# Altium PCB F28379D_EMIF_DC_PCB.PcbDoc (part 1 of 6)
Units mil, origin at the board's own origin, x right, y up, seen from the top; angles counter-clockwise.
Board outline 3000 x 1480 mil, 6 copper layers (Top Layer, Signal Layer 1, Signal Layer 2, Signal Layer 3, Signal Layer 4, Bottom Layer), stack 61.4 mil thick; 51 components, 68 nets, 414 pads, 205 vias.
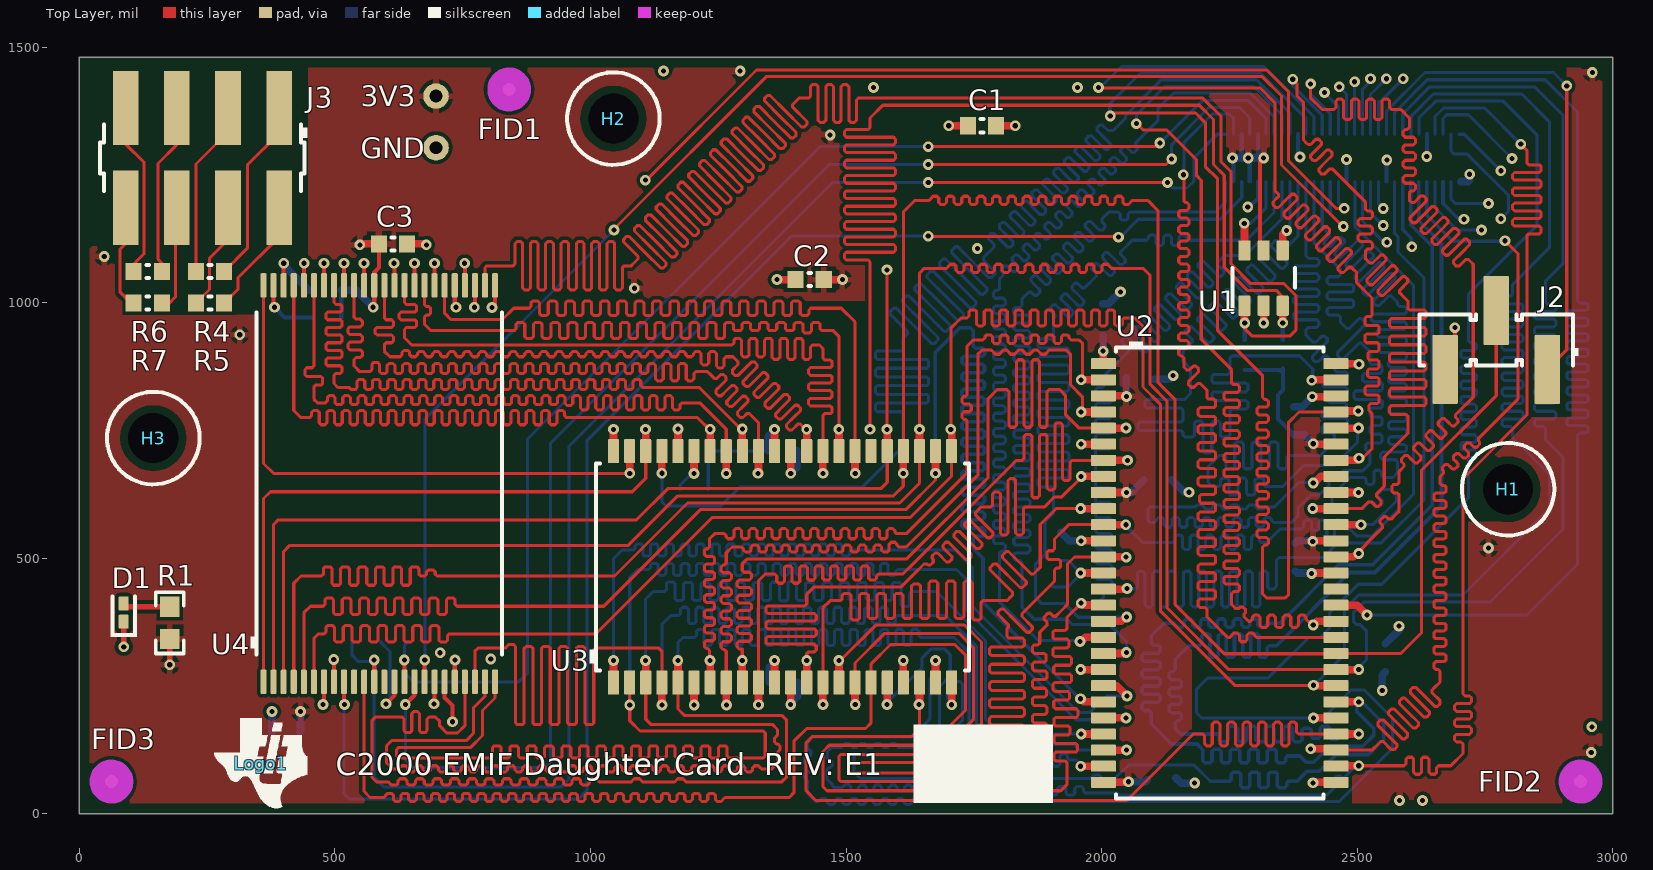
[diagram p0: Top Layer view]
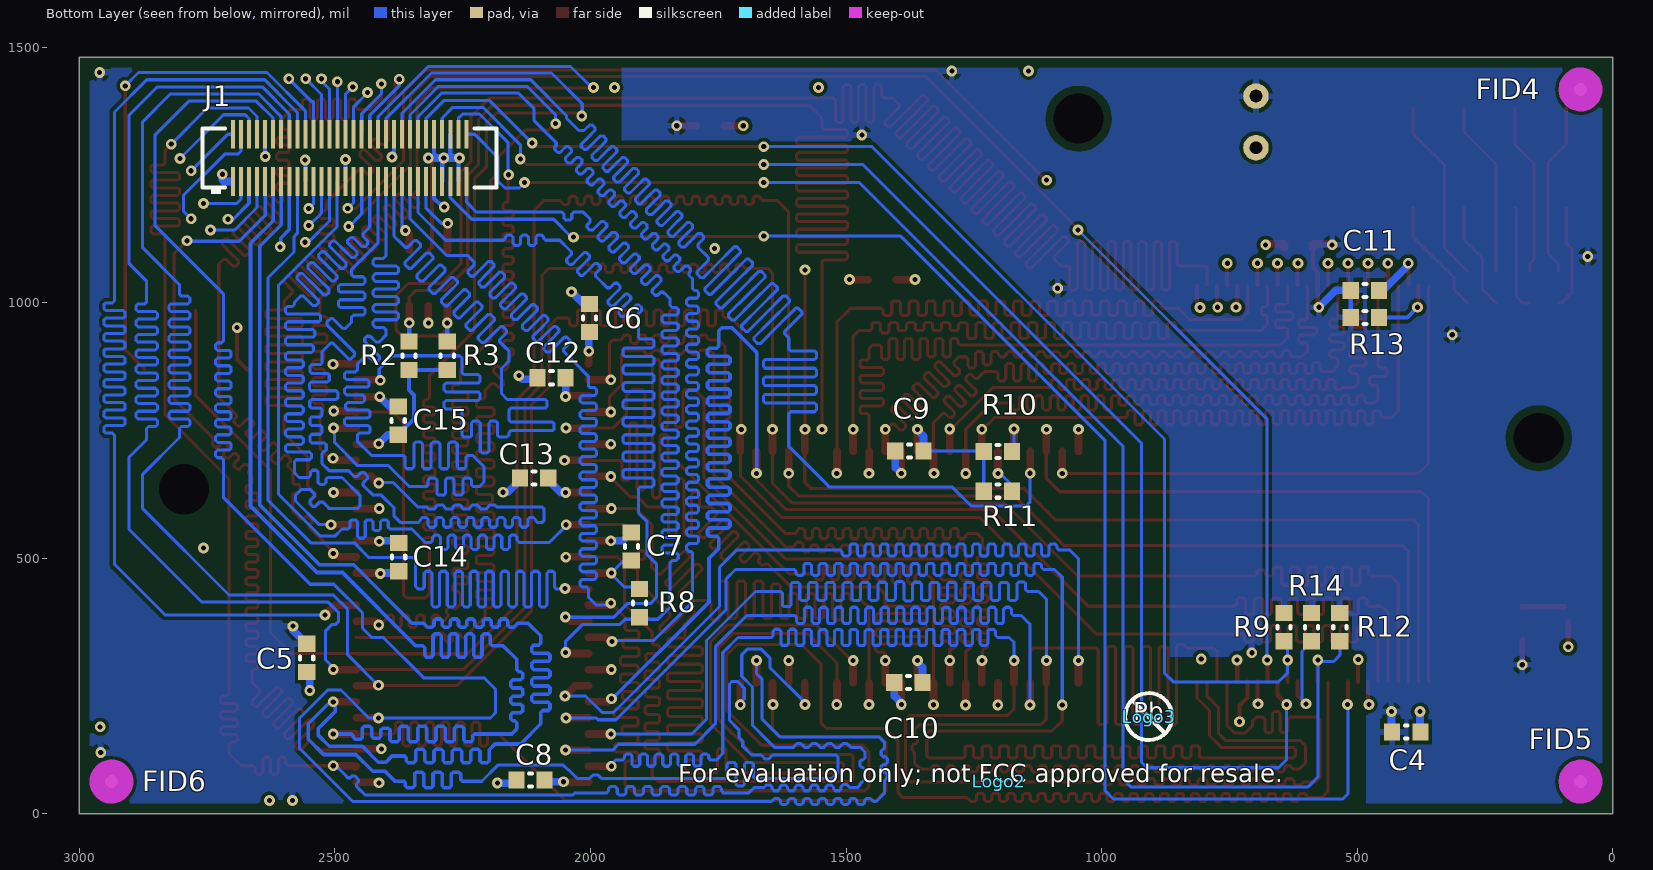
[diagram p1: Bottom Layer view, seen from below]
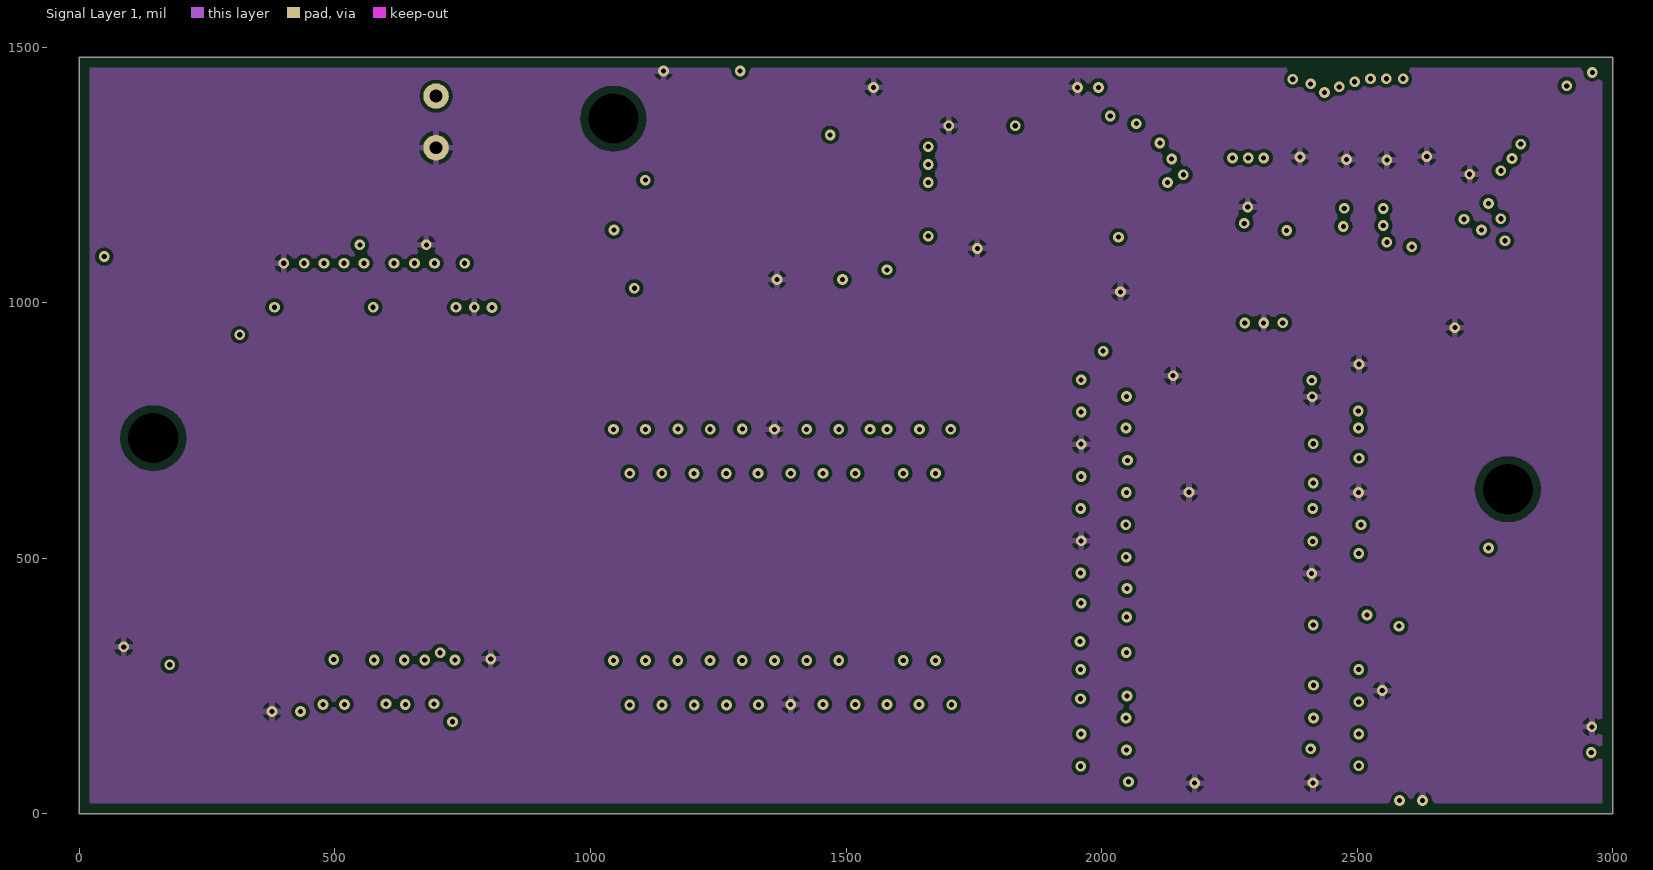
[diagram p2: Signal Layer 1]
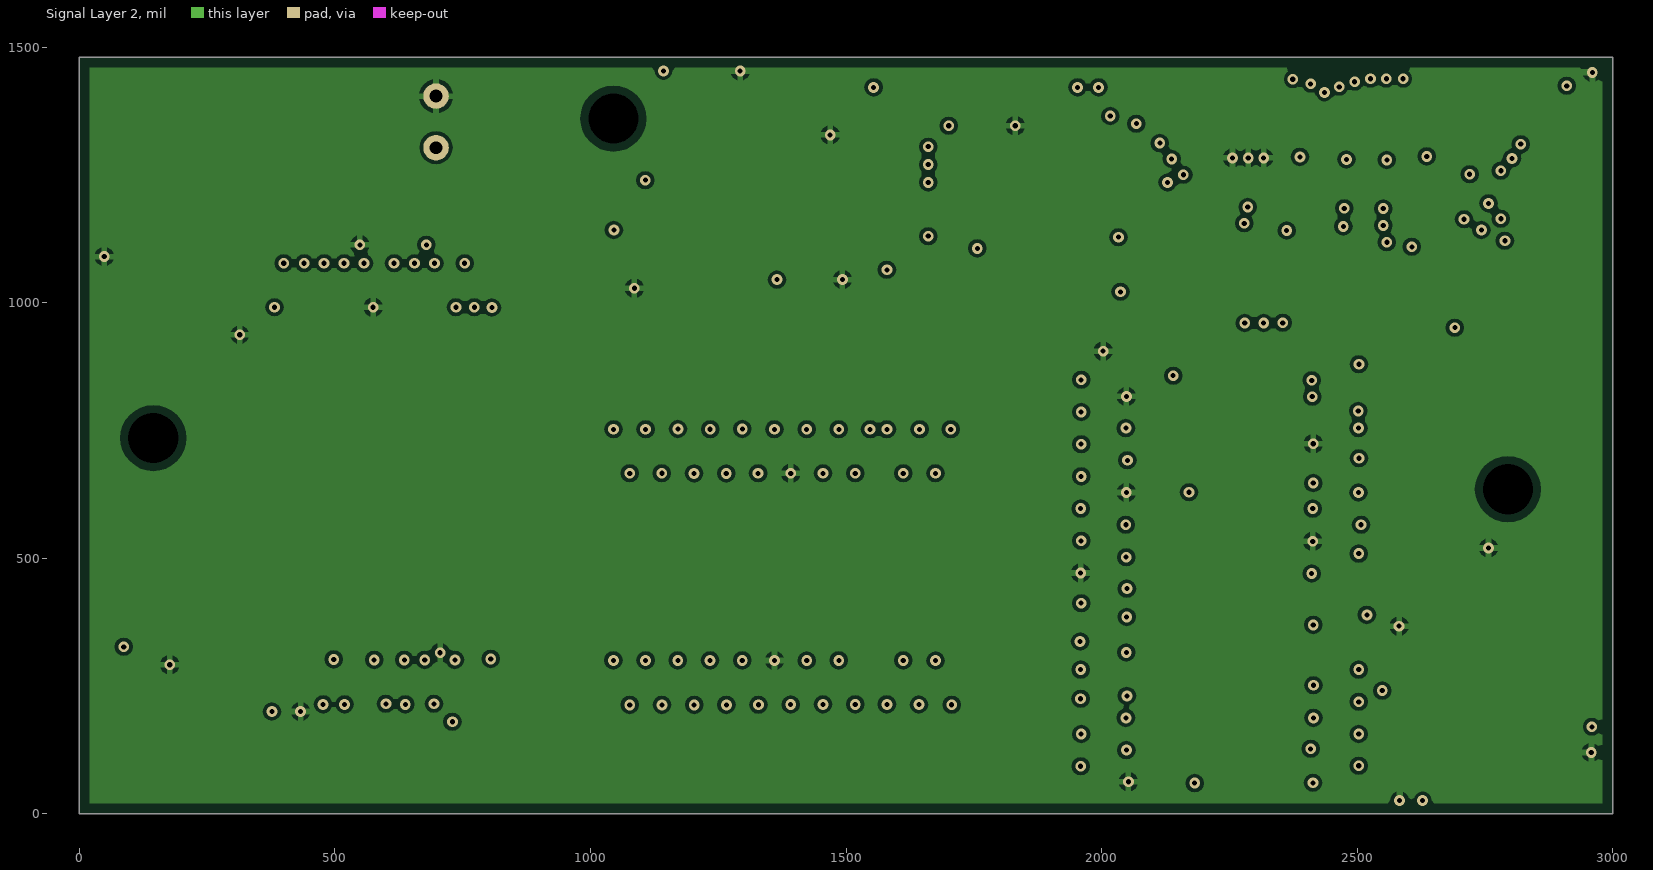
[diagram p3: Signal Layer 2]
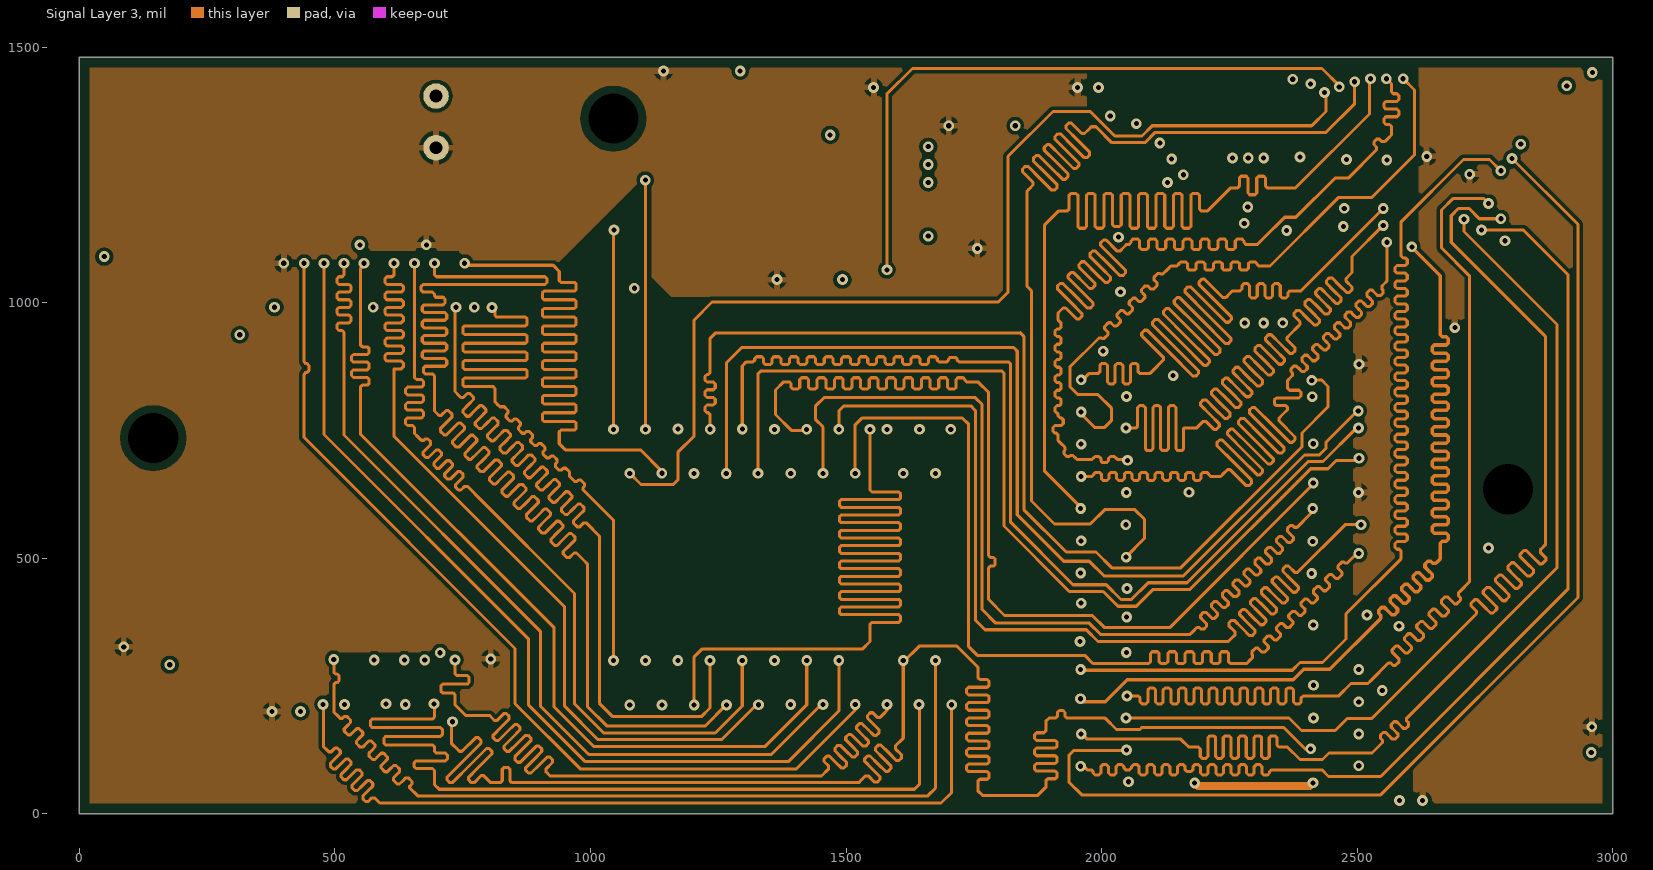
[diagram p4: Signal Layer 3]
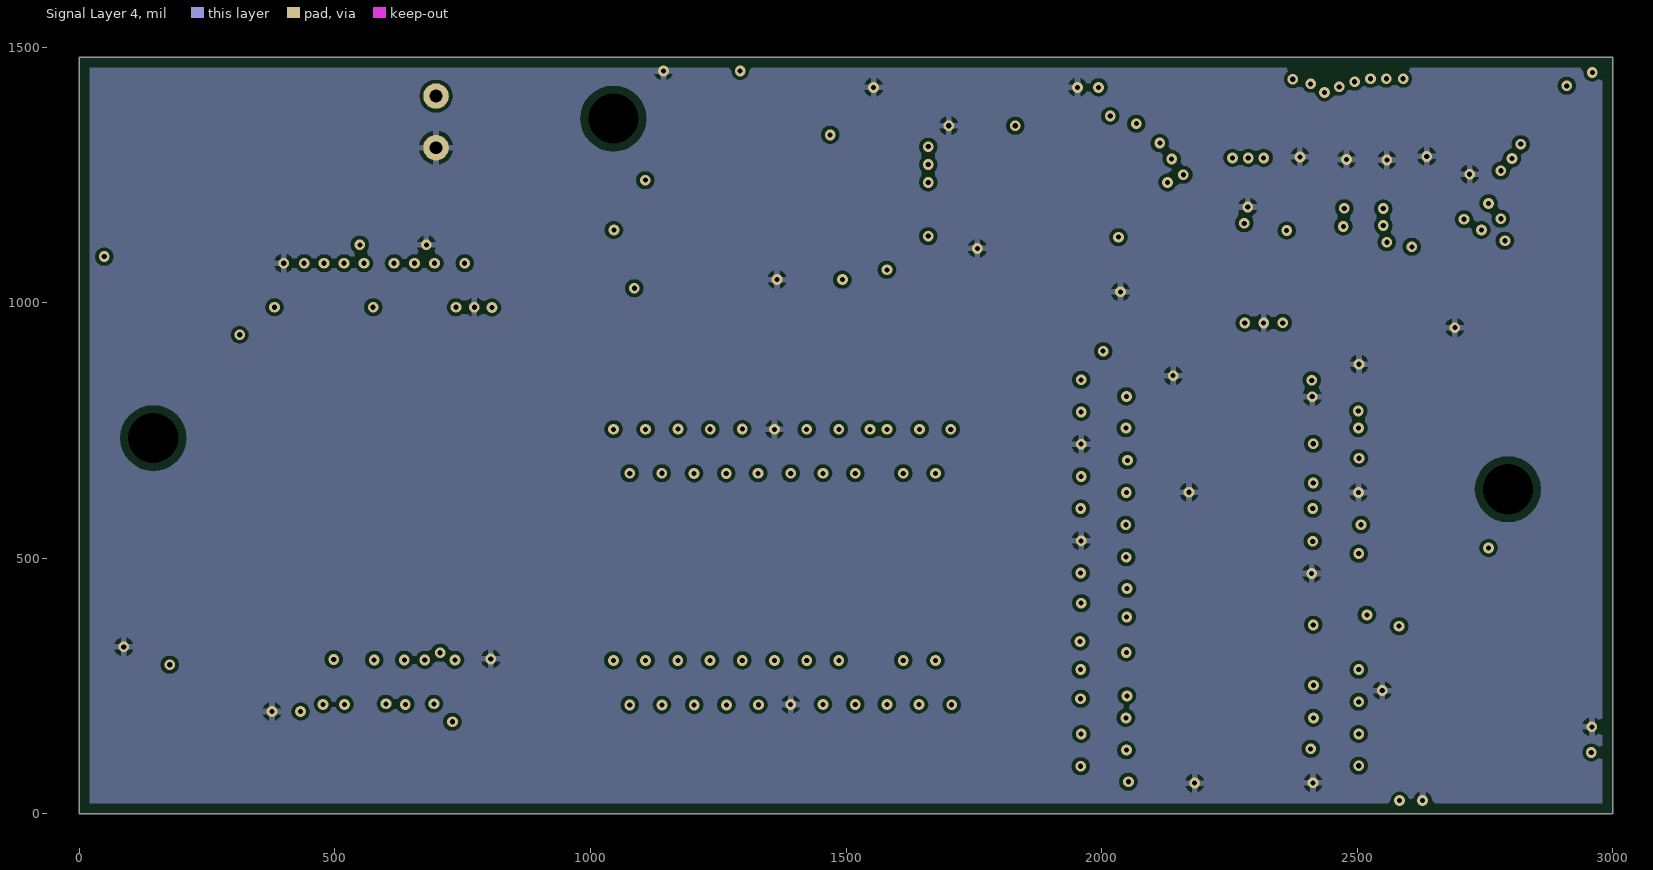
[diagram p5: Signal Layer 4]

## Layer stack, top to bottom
Top Solder: solder mask 0.5, Solder Resist, Dk 3.5
Top Layer: signal copper 1.4
Dielectric 1: prepreg 7, FR-4, Dk 4.2
Signal Layer 1: signal copper 1.4
Dielectric 2: core 14, FR-4, Dk 4.2
Signal Layer 2: signal copper 1.4
Dielectric 4: prepreg 11, FR-4, Dk 4.2
Signal Layer 3: signal copper 1.4
Dielectric 5: core 14, FR-4, Dk 4.2
Signal Layer 4: signal copper 1.4
Dielectric 3: prepreg 7, FR-4, Dk 4.2
Bottom Layer: signal copper 1.4
Bottom Solder: solder mask 0.5, Solder Resist, Dk 3.5

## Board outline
0,0 3000,0 3000,1480 0,1480

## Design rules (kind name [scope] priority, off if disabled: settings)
AcuteAngle [All] p1: minimum=4.50000000000000E+0001 checktracksonly=FALSE
AssemblyTestPointUsage [All] p1: valid=2
BoardOutlineClearance BoardOutlineClearance_MountingHoles [OnCopper and InComponentClass('Mounting Holes')] p1: gap=40
BoardOutlineClearance BoardOutlineClearance_Poly [OnCopper and IsPoly] p2: gap=20
BoardOutlineClearance [OnCopper and Not InComponentClass('Logo') and not InComponentClass('FiducialMark') and not InRegion(1000,500,4000,800) and not InPoly] p3: gap=15
Clearance Clearance_Essentra [HasFootprint('Essentra_MDLSP1-04M-01')] p1: gap=15
Clearance Clearance_Keepouts [((IsTrack Or IsArc) And Not InPoly) And IsFree and IsKeepOut vs ((IsTrack Or IsArc) And Not InPoly) And IsFree and IsKeepOut] p2: gap=0
Clearance Clearance_Poly [InPolygon] p3: gap=7
Clearance [All] p4: gap=7
ComponentClearance ComponentClearance_MountingHoles_FiducialMarks [InComponentClass('Mounting Holes') vs InComponentClass('FiducialMark')] p1: gap=50 collisioncheckmode=3 verticalgap=10 showdistances=FALSE
ComponentClearance ComponentClearance_Shunt [InComponentClass('Header') vs InComponentClass('Shunt')] p2: gap=0 collisioncheckmode=3 verticalgap=0 showdistances=FALSE
ComponentClearance ComponentClearance_Logo [InComponentClass('Logo')] p3: gap=50 collisioncheckmode=3 verticalgap=10 showdistances=FALSE
ComponentClearance ComponentClearance_ScrewToNut [(HasFootprint('NY PMS 440 0025 PH')) vs (HasFootprint('Keystone_1902C'))] p4: gap=5 collisioncheckmode=3 verticalgap=10 showdistances=FALSE
ComponentClearance ComponentClearance_MountingHoles [InComponentClass('Mounting Holes')] p5: gap=250 collisioncheckmode=3 verticalgap=100000 showdistances=FALSE
ComponentClearance ComponentClearance_SmallPassives [HasFootprint('0201*') or HasFootprint('0402*') or HasFootprint('0508') or HasFootprint('0603*') or HasFootprint('0612') or HasFootprint('0805*') or HasFootprint('0815*') or HasFootprint('0830*') or HasFootprint('1206*') or HasFootprint('1210*') or HasFootprint('1808*') or HasFootprint('1812*') or HasFootprint('1825*') or HasFootprint('2010*') or HasFootprint('2220*') or HasFootprint('2225*') or HasFootprint('2512*') or HasFootprint('2728*') or HasFootprint('3518*') vs HasFootprint('0201*') or HasFootprint('0402*') or HasFootprint('0508') or HasFootprint('0603*') or HasFootprint('0612') or HasFootprint('0805*') or HasFootprint('0815*') or HasFootprint('0830*') or HasFootprint('1206*') or HasFootprint('1210*') or HasFootprint('1808*') or HasFootprint('1812*') or HasFootprint('1825*') or HasFootprint('2010*') or HasFootprint('2220*') or HasFootprint('2225*') or HasFootprint('2512*') or HasFootprint('2728*') or HasFootprint('3518*')] p6: gap=14.96 collisioncheckmode=3 verticalgap=10 showdistances=FALSE
ComponentClearance ComponentClearance_THtoSMT [IsThruComponent vs IsSMTComponent] p7: gap=40 collisioncheckmode=3 verticalgap=30 showdistances=FALSE
ComponentClearance ComponentClearance_THtoTH [IsThruComponent vs IsThruComponent] p8: gap=30 collisioncheckmode=3 verticalgap=30 showdistances=FALSE
ComponentClearance [All] p9: gap=30 collisioncheckmode=3 verticalgap=10 showdistances=FALSE
DiffPairsRouting [All] p1: maxlimit=100 minlimit=10 mostfreqgap=10 toplayer_minwidth=15 toplayer_maxwidth=15 toplayer_prefwidth=15 midlayer1_minwidth=15 midlayer1_maxwidth=15 midlayer1_prefwidth=15 midlayer2_minwidth=15 midlayer2_maxwidth=15 midlayer2_prefwidth=15 midlayer3_minwidth=15 midlayer3_maxwidth=15 midlayer3_prefwidth=15 midlayer4_minwidth=15 midlayer4_maxwidth=15 midlayer4_prefwidth=15 bottomlayer_minwidth=15 bottomlayer_maxwidth=15 bottomlayer_prefwidth=15 maxuncoupledlength=1000
FabricationTestPointUsage TestPointUsage [All] p1: valid=2 allowmultiple=FALSE
FabricationTestpoint Testpoint [All] p1: side=3 testpointundercomponent=TRUE minsize=40 maxsize=100 preferedsize=60 minholesize=0 maxholesize=40 preferedholesize=32 testpointgrid=1 allowsidetop=TRUE allowsidebottom=TRUE usegrid=TRUE gridtolerance=0.01
FanoutControl Fanout_LCC [IsLCC] p1: bgadir=Out bgaviamode=Centered fanoutstyle=Auto fanoutdirection=Alternating viagrid=1 // Fanout_LCC (Default Rule)
FanoutControl Fanout_BGA [IsBGA] p2: bgadir=Out bgaviamode=Centered fanoutstyle=Auto fanoutdirection=Alternating viagrid=1 // Fanout_BGA (Default Rule)
FanoutControl Fanout_Default [All] p4: bgadir=Out bgaviamode=Centered fanoutstyle=Auto fanoutdirection=Alternating viagrid=1 // Fanout_Default (Default Rule)
FanoutControl Fanout_Small [(CompPinCount < 5)] p5: bgadir=Out bgaviamode=Centered fanoutstyle=Auto fanoutdirection=OutThenIn viagrid=1 // Fanout_Small (Default Rule)
HoleSize [All] p1: absolutevalues=TRUE maxlimit=251 minlimit=7.87 maxpercent=80.000 minpercent=20.000
MatchedLengths "Matched Length" [InNetClass('FLASH_Net')] p1: tolerance=30 checknetsindiffpair=FALSE checkdiffpairvsdiffpair=TRUE checkxsignals=TRUE checkothers=TRUE
MinimumAnnularRing MinimumAnnularRing_ThermalPadVias [IsVia and InAnyComponent] p1: minimumring=5.91
MinimumAnnularRing [All] p2: minimumring=5
MinimumSolderMaskSliver MinimumSolderMaskSliver_Logo [InComponentClass('Logo') vs InComponentClass('Logo')] p1: minsoldermaskwidth=0.7
MinimumSolderMaskSliver [All] p2: minsoldermaskwidth=3.8
PlaneClearance [All] p1: clearance=8
PlaneConnect [All] p1: planeconnectstyle=Relief reliefexpansion=10 reliefentries=4 reliefconductorwidth=12 reliefairgap=8
PolygonConnect [All] p1: connectstyle=Relief reliefconductorwidth=12 reliefentries=4 polygonreliefangle="90 Angle" airgapwidth=8
RoutingVias ThermalPadVias [IsVia and InAnyComponent] p1: holewidth=7.87 width=19.68 viastyle="Through Hole" minholewidth=7.87 minwidth=19.68 maxholewidth=12.99 maxwidth=23.62
RoutingVias [All] p2: holewidth=10 width=20 viastyle="Through Hole" minholewidth=7.87 minwidth=20 maxholewidth=40 maxwidth=65
SilkToBoardRegionClearance [Not ((IsComment or IsDesignator) And (Hide <> 'False')) and not InRegion(1000,500,4000,800)] p1:
SilkToSilkClearance SilkToSilkClearance_Pb-FreeLogo [(HasFootprint('Pb-Free_Overlay_Medium') OR HasFootprint('Pb-Free_Overlay_Small')) vs (HasFootprint('Pb-Free_Overlay_Medium') OR HasFootprint('Pb-Free_Overlay_Small'))] p1: silktosilkclearance=0
SilkToSilkClearance [All] p2: silktosilkclearance=4
SilkToSolderMaskClearance SilkToComponentPadClearance [(IsPad or IsFill or IsRegion) and InAnycomponent] p1: minsilkscreentomaskgap=5 clearancetoexposedcopper=TRUE
SilkToSolderMaskClearance "Silk to Solder Mask Opening" [All] p2: minsilkscreentomaskgap=4 clearancetoexposedcopper=FALSE
SolderMaskExpansion [All] p1: expansion=1.97
Width "Power Route" [InNetClass('Power')] p1: maxlimit=20 minlimit=6 preferedwidth=15
Width [All] p2: maxlimit=100 minlimit=6 preferedwidth=6 checkconnectedcopper=TRUE
14 further rules are at their usual default settings.

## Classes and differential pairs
component class Logo: Logo1
component class FiducialMark: FID1 FID2 FID3 FID4 FID5 FID6
net class FLASH_Net: /EM_OE /EM_WE EM_A0 EM_A1 EM_A2 EM_A3 EM_A4 EM_A5 EM_A6 EM_A7 EM_A8 EM_A9 EM_A10 EM_A11 EM_BA1 EM_D0 EM_D1 EM_D2 EM_D3 EM_D4 EM_D5 EM_D6 EM_D7 EM_D8 EM_D9 EM_D10 EM_D11 EM_D12 EM_D13 EM_D14 EM_D15
net class ASRAM_Net: /EM_OE /EM_WE EM_A0 EM_A1 EM_A2 EM_A3 EM_A4 EM_A5 EM_A6 EM_A7 EM_A8 EM_A9 EM_A10 EM_A11 EM_BA1 EM_D0 EM_D1 EM_D2 EM_D3 EM_D4 EM_D5 EM_D6 EM_D7 EM_D8 EM_D9 EM_D10 EM_D11 EM_D12 EM_D13 EM_D14 EM_D15
net class SDRAM_Net: /EM_CS0 /EM_WE EM_A0 EM_A1 EM_A2 EM_A3 EM_A4 EM_A5 EM_A6 EM_A7 EM_A8 EM_A9 EM_A10 EM_A11 EM_A13_CAS EM_A14_RAS EM_A15_DQM0 EM_A16_DQM1 EM_BA0 EM_BA1 EM_CLK EM_D0 EM_D1 EM_D2 EM_D3 EM_D4 EM_D5 EM_D6 EM_D7 EM_D8 EM_D9 EM_D10 EM_D11 EM_D12 EM_D13 EM_D14 EM_D15 EM_SDCKE
net class Power_Net: GND VCC_3V3
component class F28379D_EMIF_EVM_Hardware: FID1 FID2 FID3 FID4 FID5 FID6 H1 H2 H3 Logo1 Logo2 Logo3
component class F28379D_EMIF_Memory: 3V3 C1 C2 C3 C4 C5 C6 C7 C8 C9 C10 C11 C12 C13 C14 C15 D1 GND J1 J2 J3 R1 R2 R3 R4 R5 R6 R7 R8 R9 R10 R11 R12 R13 R14 R? TP2 U1 U2 U3 U4
component class Header: J2 J3

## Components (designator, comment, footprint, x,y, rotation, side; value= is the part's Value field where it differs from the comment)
3V3 "TESTPOINT" TP_50MIL-25MILHOLE 698,1404 r0 top
C1 "C1608X5R1A106M080AC" 0603L 1766,1346 r180 top
C2 "C1608X5R1A106M080AC" 0603L 1429,1045 r180 top
C3 "C1608X5R1A106M080AC" 0603L 614,1115 r0 top
C4 "C1608X5R1A106M080AC" 0603L 404,160 r180 bottom
C5 "C1608X5R1A106M080AC" 0603L 2555,305 r270 bottom
C6 "GRM188R71A225KE15D" 0603L 2002,970 r90 bottom
C7 "GRM188R71A225KE15D" 0603L 1920,523 r90 bottom
C8 "GRM188R71A225KE15D" 0603L 2117,66 r0 bottom
C9 "GRM188R71A225KE15D" 0603L 1376,710 r180 bottom
C10 "GRM188R71A225KE15D" 0603L 1378,257 r0 bottom
C11 "GRM188R71A225KE15D" 0603L 485,1024 r180 bottom
C12 "GRM188R71A225KE15D" 0603L 2076,853 r0 bottom
C13 "GRM188R71A225KE15D" 0603L 2110,657 r0 bottom
C14 "GRM188R71A225KE15D" 0603L 2375,502 r270 bottom
C15 "GRM188R71A225KE15D" 0603L 2376,769 r90 bottom
D1 "APHHS1005CGCK" APHHS1005_Green 87,393.5 r270 top
FID1 "Fiducial" Fiducial6.4-20 841,1417 r0 top
FID2 "Fiducial" Fiducial6.4-20 2937,63 r0 top
FID3 "Fiducial" Fiducial6.4-20 63,63 r0 top
FID4 "Fiducial" Fiducial6.4-20 63,1417 r180 bottom
FID5 "Fiducial" Fiducial6.4-20 63,63 r180 bottom
FID6 "Fiducial" Fiducial6.4-20 2937,63 r180 bottom
GND "TESTPOINT" TP_50MIL-25MILHOLE 698,1303 r0 top
H1 "MDLSP1-04M-01" Essentra_MDLSP1-04M-01 2795,635 r0 top locked
H2 "MDLSP1-04M-01" Essentra_MDLSP1-04M-01 1045,1360 r0 top locked
H3 "MDLSP1-04M-01" Essentra_MDLSP1-04M-01 145,735 r0 top locked
J1 "DF40HC(4.0)-60DS-0.4V(51)" Hirose_DF40HC-4_0-60DS-0_4V_Reverse 2471,1283 r180 bottom
J2 "TSM-103-01-L-SV-P-TR" Samtec_TSM-103-01-x-SV-P 2772,927 r180 top
J3 "TSM-104-01-L-DV" Samtec_TSM-104-01-x-DV 241,1283 r270 top
Logo1 "Texas Instruments" TI_Symbol_Overlay_Small 355,99 r0 top
Logo2 "FCC disclaimer" FCC_disclaimer 1201,64 r180 bottom
Logo3 "Pb-Free Symbol" Pb-Free_Overlay_Small 908,190 r180 bottom
R1 "CRCW0603820RJNEA" 0603 177,373.5 r270 top
R2 "RC0603JR-0747KL" 0603L 2355,896 r270 bottom
R3 "RC0603JR-0747KL" 0603L 2280,896 r270 bottom
R4 "CRCW06030000Z0EA" 0603L 256,1061 r0 top
R5 "CRCW06030000Z0EA" 0603L 256,999 r180 top
R6 "CRCW06030000Z0EA" 0603L 134,1061 r0 top
R7 "CRCW06030000Z0EA" 0603L 134,999 r180 top
R8 "RC0603JR-0747KL" 0603L 1904,412 r90 bottom
R9 "RC0603JR-0747KL" 0603L 643,365 r90 bottom
R10 "RC0603JR-0747KL" 0603L 1203,709 r180 bottom
R11 "RC0603JR-0747KL" 0603L 1203,631 r180 bottom
R12 "RC0603JR-0747KL" 0603L 534,365 r270 bottom
R13 "RC0603JR-0747KL" 0603L 485,971 r180 bottom
R14 "RC0603JR-0747KL" 0603L 589,365 r270 bottom
U1 "TS5A3159DBVR" DBV0006A_N 2317,1048 r90 top
U2 "AS4C16M16SA-6TIN" TSOP-2_54 2231,471 r0 top
U3 "IS61WV25616EDBLL-10TLI" TSOP-2_44 1376,483 r90 top
U4 "S29AL016J70TFI020" TSOP-48 587,646 r90 top

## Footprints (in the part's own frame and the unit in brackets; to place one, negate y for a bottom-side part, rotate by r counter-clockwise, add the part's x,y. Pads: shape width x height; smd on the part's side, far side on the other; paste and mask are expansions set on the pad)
0603 [mm] "0603 from SM-752 data"
  rect 1x0.95 smd: 1(-0.8,0) 2(0.8,0)
  silkscreen extent -1.52,-0.69 1.52,0.69, body extent -0.87,-0.47 0.87,0.47, height 1
0603L [mm] "0603 from SM-752 data"
  rect 0.8x0.85 smd: 1(-0.7,0) 2(0.7,0)
  silkscreen extent -0.07,-0.33 0.07,0.33, body extent -0.87,-0.47 0.87,0.47, height 1
APHHS1005_Green [mm] "SMD, 2-Leads, Body 1x0.5mm"
  rrect20% 0.7x0.5 smd: 1(-0.45,0) 2(0.45,0)
  silkscreen extent -0.8,-0.65 1.2,0.65, body extent -0.5,-0.25 0.5,0.25, height 0.5
DBV0006A_N [mm] "SOT23, 6-Leads, Body 2.9x1.6mm, Pitch 0.95mm, Lead Span 2.8mm, IPC Medium Density"
  rrect17% 1x0.6 smd: 1(-1.375,0.95) 2(-1.375,0) 3(-1.375,-0.95) 4(1.375,-0.95) 5(1.375,0) 6(1.375,0.95)
  silkscreen extent -1.67,-1.55 0.5,1.55, body extent -1.42,-1.46 1.42,1.46, height 1.12
Essentra_MDLSP1-04M-01 [mm] "Board Support Snap Lock"
  round 0 hole 2.5 unplated: 1(0,0)
  silkscreen extent -2.3,-2.3 2.3,2.3, body extent -2.3,-2.3 2.3,2.3, height 7.7
FCC_disclaimer [mil]
Fiducial6.4-20 [mil]
  round 25 smd mask+26.87: 1(0,0)
  Top Layer keep-out circle w46.37: c0,0 r19.68
Hirose_DF40HC-4_0-60DS-0_4V_Reverse [mm] "Receptacle, 0.4mm, 30x2, SMT"
  rect 0.2x0.7 on Bottom Paste mask-1: 1(-5.8,-1.54) 2(-5.8,1.54) 3(-5.4,-1.54) 4(-5.4,1.54) 5(-5,-1.54) 6(-5,1.54) 7(-4.6,-1.54) 8(-4.6,1.54) 9(-4.2,-1.54) 10(-4.2,1.54) 11(-3.8,-1.54) 12(-3.8,1.54) 13(-3.4,-1.54) 14(-3.4,1.54) 15(-3,-1.54) 16(-3,1.54) 17(-2.6,-1.54) 18(-2.6,1.54) 19(-2.2,-1.54) 20(-2.2,1.54) 21(-1.8,-1.54) 22(-1.8,1.54) 23(-1.4,-1.54) 24(-1.4,1.54) 25(-1,-1.54) 26(-1,1.54) 27(-0.6,-1.54) 28(-0.6,1.54) 29(-0.2,-1.54) 30(-0.2,1.54) 31(0.2,-1.54) 32(0.2,1.54) 33(0.6,-1.54) 34(0.6,1.54) 35(1,-1.54) 36(1,1.54) 37(1.4,-1.54) 38(1.4,1.54) 39(1.8,-1.54) 40(1.8,1.54) 41(2.2,-1.54) 42(2.2,1.54) 43(2.6,-1.54) 44(2.6,1.54) 45(3,-1.54) 46(3,1.54) 47(3.4,-1.54) 48(3.4,1.54) 49(3.8,-1.54) 50(3.8,1.54) 51(4.2,-1.54) 52(4.2,1.54) 53(4.6,-1.54) 54(4.6,1.54) 55(5,-1.54) 56(5,1.54) 57(5.4,-1.54) 58(5.4,1.54) 59(5.8,-1.54) 60(5.8,1.54)
  rect 0.2x0.7 on Bottom Solder mask-1: 1(-5.8,-1.54) 2(-5.8,1.54) 3(-5.4,-1.54) 4(-5.4,1.54) 5(-5,-1.54) 6(-5,1.54) 7(-4.6,-1.54) 8(-4.6,1.54) 9(-4.2,-1.54) 10(-4.2,1.54) 11(-3.8,-1.54) 12(-3.8,1.54) 13(-3.4,-1.54) 14(-3.4,1.54) 15(-3,-1.54) 16(-3,1.54) 17(-2.6,-1.54) 18(-2.6,1.54) 19(-2.2,-1.54) 20(-2.2,1.54) 21(-1.8,-1.54) 22(-1.8,1.54) 23(-1.4,-1.54) 24(-1.4,1.54) 25(-1,-1.54) 26(-1,1.54) 27(-0.6,-1.54) 28(-0.6,1.54) 29(-0.2,-1.54) 30(-0.2,1.54) 31(0.2,-1.54) 32(0.2,1.54) 33(0.6,-1.54) 34(0.6,1.54) 35(1,-1.54) 36(1,1.54) 37(1.4,-1.54) 38(1.4,1.54) 39(1.8,-1.54) 40(1.8,1.54) 41(2.2,-1.54) 42(2.2,1.54) 43(2.6,-1.54) 44(2.6,1.54) 45(3,-1.54) 46(3,1.54) 47(3.4,-1.54) 48(3.4,1.54) 49(3.8,-1.54) 50(3.8,1.54) 51(4.2,-1.54) 52(4.2,1.54) 53(4.6,-1.54) 54(4.6,1.54) 55(5,-1.54) 56(5,1.54) 57(5.4,-1.54) 58(5.4,1.54) 59(5.8,-1.54) 60(5.8,1.54)
  rect 0.2x1.43 smd paste-1 mask-1: 1(-5.8,-1.175) 2(-5.8,1.175) 3(-5.4,-1.175) 4(-5.4,1.175) 5(-5,-1.175) 6(-5,1.175) 7(-4.6,-1.175) 8(-4.6,1.175) 9(-4.2,-1.175) 10(-4.2,1.175) 11(-3.8,-1.175) 12(-3.8,1.175) 13(-3.4,-1.175) 14(-3.4,1.175) 15(-3,-1.175) 16(-3,1.175) 17(-2.6,-1.175) 18(-2.6,1.175) 19(-2.2,-1.175) 20(-2.2,1.175) 21(-1.8,-1.175) 22(-1.8,1.175) 23(-1.4,-1.175) 24(-1.4,1.175) 25(-1,-1.175) 26(-1,1.175) 27(-0.6,-1.175) 28(-0.6,1.175) 29(-0.2,-1.175) 30(-0.2,1.175) 31(0.2,-1.175) 32(0.2,1.175) 33(0.6,-1.175) 34(0.6,1.175) 35(1,-1.175) 36(1,1.175) 37(1.4,-1.175) 38(1.4,1.175) 39(1.8,-1.175) 40(1.8,1.175) 41(2.2,-1.175) 42(2.2,1.175) 43(2.6,-1.175) 44(2.6,1.175) 45(3,-1.175) 46(3,1.175) 47(3.4,-1.175) 48(3.4,1.175) 49(3.8,-1.175) 50(3.8,1.175) 51(4.2,-1.175) 52(4.2,1.175) 53(4.6,-1.175) 54(4.6,1.175) 55(5,-1.175) 56(5,1.175) 57(5.4,-1.175) 58(5.4,1.175) 59(5.8,-1.175) 60(5.8,1.175)
  silkscreen extent -7.3,-1.8 7.3,1.47, body extent -7.3,-1.69 7.3,1.69, height 3.9
Pb-Free_Overlay_Small [mil]
  silkscreen extent -46,-46 46,46
Samtec_TSM-103-01-x-SV-P [mm] "Header, 2.54mm, 3x1, SMT"
  rrect8% 1.27x3.43 smd: 1(-2.54,1.46) 2(0,-1.46) 3(2.54,1.46)
  silkscreen extent -4.1,-1.27 3.81,1.27, body extent -3.81,-2.41 3.81,2.41, height 9.97
Samtec_TSM-104-01-x-DV [mm] "Header, 2.54mm, 4x2, SMT"
  rect 3.68x1.27 smd: 1(-2.475,3.81) 2(2.475,3.81) 3(-2.475,1.27) 4(2.475,1.27) 5(-2.475,-1.27) 6(2.475,-1.27) 7(-2.475,-3.81) 8(2.475,-3.81)
  silkscreen extent -1.65,-5.08 1.65,5.22, body extent -3.85,-5.08 3.85,5.08, height 9.65
TI_Symbol_Overlay_Small [mil]
  silkscreen extent -90,-88 91,88
TP_50MIL-25MILHOLE [mil]
  round 50 hole 25: 1(0,0)
TSOP-2_44 [mm] "TSOP, 44-Leads, Body 18.41x10.16mm, Pitch 0.8mm"
  rrect18% 1.2x0.55 smd: 1(-5.75,8.4) 2(-5.75,7.6) 3(-5.75,6.8) 4(-5.75,6) 5(-5.75,5.2) 6(-5.75,4.4) 7(-5.75,3.6) 8(-5.75,2.8) 9(-5.75,2) 10(-5.75,1.2) 11(-5.75,0.4) 12(-5.75,-0.4) 13(-5.75,-1.2) 14(-5.75,-2) 15(-5.75,-2.8) 16(-5.75,-3.6) 17(-5.75,-4.4) 18(-5.75,-5.2) 19(-5.75,-6) 20(-5.75,-6.8) 21(-5.75,-7.6) 22(-5.75,-8.4) 23(5.75,-8.4) 24(5.75,-7.6) 25(5.75,-6.8) 26(5.75,-6) 27(5.75,-5.2) 28(5.75,-4.4) 29(5.75,-3.6) 30(5.75,-2.8) 31(5.75,-2) 32(5.75,-1.2) 33(5.75,-0.4) 34(5.75,0.4) 35(5.75,1.2) 36(5.75,2) 37(5.75,2.8) 38(5.75,3.6) 39(5.75,4.4) 40(5.75,5.2) 41(5.75,6) 42(5.75,6.8) 43(5.75,7.6) 44(5.75,8.4)
  silkscreen extent -5.15,-9.27 5.15,9.6, body extent -5.88,-9.25 5.88,9.25, height 1.2
TSOP-2_54 [mm] "TSOP, 54-Leads, Body 22.22x10.16mm, Pitch 0.8mm"
  rrect18% 1.25x0.55 smd: 1(-5.775,10.4) 2(-5.775,9.6) 3(-5.775,8.8) 4(-5.775,8) 5(-5.775,7.2) 6(-5.775,6.4) 7(-5.775,5.6) 8(-5.775,4.8) 9(-5.775,4) 10(-5.775,3.2) 11(-5.775,2.4) 12(-5.775,1.6) 13(-5.775,0.8) 14(-5.775,0) 15(-5.775,-0.8) 16(-5.775,-1.6) 17(-5.775,-2.4) 18(-5.775,-3.2) 19(-5.775,-4) 20(-5.775,-4.8) 21(-5.775,-5.6) 22(-5.775,-6.4) 23(-5.775,-7.2) 24(-5.775,-8) 25(-5.775,-8.8) 26(-5.775,-9.6) 27(-5.775,-10.4) 28(5.775,-10.4) 29(5.775,-9.6) 30(5.775,-8.8) 31(5.775,-8) 32(5.775,-7.2) 33(5.775,-6.4) 34(5.775,-5.6) 35(5.775,-4.8) 36(5.775,-4) 37(5.775,-3.2) 38(5.775,-2.4) 39(5.775,-1.6) 40(5.775,-0.8) 41(5.775,0) 42(5.775,0.8) 43(5.775,1.6) 44(5.775,2.4) 45(5.775,3.2) 46(5.775,4) 47(5.775,4.8) 48(5.775,5.6) 49(5.775,6.4) 50(5.775,7.2) 51(5.775,8) 52(5.775,8.8) 53(5.775,9.6) 54(5.775,10.4)
  silkscreen extent -5.15,-11.2 5.15,11.5, body extent -5.15,-11.2 5.15,11.2, height 1.2
TSOP-48 [mm] "TSOP, 48-Leads, Body 12x18.4mm, Pitch 0.5mm"
  rrect33% 1.2x0.3 smd: 1(-9.85,5.75) 2(-9.85,5.25) 3(-9.85,4.75) 4(-9.85,4.25) 5(-9.85,3.75) 6(-9.85,3.25) 7(-9.85,2.75) 8(-9.85,2.25) 9(-9.85,1.75) 10(-9.85,1.25) 11(-9.85,0.75) 12(-9.85,0.25) 13(-9.85,-0.25) 14(-9.85,-0.75) 15(-9.85,-1.25) 16(-9.85,-1.75) 17(-9.85,-2.25) 18(-9.85,-2.75) 19(-9.85,-3.25) 20(-9.85,-3.75) 21(-9.85,-4.25) 22(-9.85,-4.75) 23(-9.85,-5.25) 24(-9.85,-5.75) 25(9.85,-5.75) 26(9.85,-5.25) 27(9.85,-4.75) 28(9.85,-4.25) 29(9.85,-3.75) 30(9.85,-3.25) 31(9.85,-2.75) 32(9.85,-2.25) 33(9.85,-1.75) 34(9.85,-1.25) 35(9.85,-0.75) 36(9.85,-0.25) 37(9.85,0.25) 38(9.85,0.75) 39(9.85,1.25) 40(9.85,1.75) 41(9.85,2.25) 42(9.85,2.75) 43(9.85,3.25) 44(9.85,3.75) 45(9.85,4.25) 46(9.85,4.75) 47(9.85,5.25) 48(9.85,5.75)
  silkscreen extent -8.5,-6.1 8.5,6.4, body extent -10,-6.1 10,6.1, height 1.2

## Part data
3V3 GND: "TEST POINT.  No entry in BOM."
C1 C2 C3 C4 C5: "CAP, CERM, 10 µF, 10 V, +/- 20%, X5R, 0603"
C6 C7 C8 C9 C10 C11 C12 C13 C14 C15: "CAP, CERM, 2.2 µF, 10 V, +/- 10%, X7R, 0603"
D1: "LED, Green, SMD"
FID1 FID2 FID3 FID4 FID5 FID6: "Fiducial mark.  There is nothing to buy or mount."
H1 H2 H3: "Snap Lock, Nylon, 0.157\" (4.00mm)"
J1: "Receptacle, 0.4mm, 30x2, Gold, SMT"
J2: "Header, 2.54mm, 3x1, Gold, SMT"
J3: "Header, 2.54mm, 4x2, Gold, SMT"
Logo1: library part TI_Logo, "Texas Instrument Corporate Signature"
Logo2: library part FCC_disclaimer, "FCC_disclaimer"
Logo3: library part Pb-Free
R1: "RES, 820, 5%, 0.1 W, 0603"
R2 R3 R8 R9 R10 R11 R12 R13 R14: "RES, 47 k, 5%, 0.1 W, 0603"
R4 R5 R6 R7: "RES, 0, 5%, 0.1 W, 0603"
U1: "1-Ohm SPDT Analog Switch, DBV0006A (SOT-23-6)"
U2: "256M - (16Mx16bit) Synchronous DRAM (SDRAM)"
U3: "256K x 16 High Speed Asynchronous CMOS Static RAM with ECC"
U4: "16 Mbit (2 M x 8-Bit/1 M x 16-Bit), 3 V Boot Sector Flash"

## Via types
v1: diameter 21, hole 10, Top Layer to Bottom Layer, 204 vias
v2: diameter 20, hole 10, Top Layer to Bottom Layer, 1 vias

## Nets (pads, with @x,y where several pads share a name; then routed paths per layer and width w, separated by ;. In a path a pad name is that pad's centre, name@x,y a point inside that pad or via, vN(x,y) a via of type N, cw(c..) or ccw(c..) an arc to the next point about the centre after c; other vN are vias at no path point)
/EM_CS0: J1.59@2242.65,1236.74 R8.1 U2.19 | length 2691.6
  Top Layer w15: U2.19@2003.64,313.52 2046.48,313.52 v1(2048.48,315.52)
  Bottom Layer w6: v1@2048.48,313.52 v1(2048.48,315.52) 2048.48,337.52 2016,370 1943,370 1932.5,380.5 1868,380.5 1844,404.5 1844,488 1844,491.75 1840.25,495.5 1831.9,495.5 1828.15,499.25 1828.15,506.75 1831.9,510.5 1844,510.5 1856.1,510.5 1859.85,514.25 1859.85,521.75 1856.1,525.5 1844,525.5 1831.9,525.5 1828.15,529.25 1828.15,536.75 1831.9,540.5 1844,540.5 1856.1,540.5 1859.85,544.25 1859.85,551.75 1856.1,555.5 1844,555.5 1831.9,555.5 1828.15,559.25 1828.15,566.75 1831.9,570.5 1844,570.5 1856.1,570.5 1859.85,574.25 1859.85,581.75 1856.1,585.5 1844,585.5 1831.9,585.5 1828.15,589.25 1828.15,596.75 1831.9,600.5 1844,600.5 1856.1,600.5 1859.85,604.25 1859.85,611.75 1856.1,615.5 1844,615.5 1831.9,615.5 1828.15,619.25 1828.15,626.75 1831.9,630.5 1844,630.5 1856.1,630.5 1859.85,634.25 1859.85,641.75 1856.1,645.5 1844,645.5 1831.9,645.5 1828.15,649.25 1828.15,656.75 1831.9,660.5 1844,660.5 1856.1,660.5 1859.85,664.25 1859.85,671.75 1856.1,675.5 1844,675.5 1831.9,675.5 1828.15,679.25 1828.15,686.75 1831.9,690.5 1844,690.5 1856.1,690.5 1859.85,694.25 1859.85,701.75 1856.1,705.5 1844,705.5 1831.9,705.5 1828.15,709.25 1828.15,716.75 1831.9,720.5 1844,720.5 1856.1,720.5 1859.85,724.25 1859.85,731.75 1856.1,735.5 1844,735.5 1831.9,735.5 1828.15,739.25 1828.15,746.75 1831.9,750.5 1844,750.5 1856.1,750.5 1859.85,754.25 1859.85,761.75 1856.1,765.5 1844,765.5 1831.9,765.5 1828.15,769.25 1828.15,776.75 1831.9,780.5 1844,780.5 1856.1,780.5 1859.85,784.25 1859.85,791.75 1856.1,795.5 1844,795.5 1831.9,795.5 1828.15,799.25 1828.15,806.75 1831.9,810.5 1844,810.5 1856.1,810.5 1859.85,814.25 1859.85,821.75 1856.1,825.5 1844,825.5 1831.9,825.5 1828.15,829.25 1828.15,836.75 1831.9,840.5 1844,840.5 1856.1,840.5 1859.85,844.25 1859.85,851.75 1856.1,855.5 1844,855.5 1831.9,855.5 1828.15,859.25 1828.15,866.75 1831.9,870.5 1844,870.5 1856.1,870.5 1859.85,874.25 1859.85,881.75 1856.1,885.5 1844,885.5 1831.9,885.5 1828.15,889.25 1828.15,896.75 1831.9,900.5 1844,900.5 1856.1,900.5 1859.85,904.25 1859.85,911.75 1856.1,915.5 1844,915.5 1831.9,915.5 1828.15,919.25 1828.15,926.75 1831.9,930.5 1844,930.5 1856.1,930.5 1859.85,934.25 1859.85,941.75 1856.1,945.5 1844,945.5 1831.9,945.5 1828.15,949.25 1828.15,956.75 1831.9,960.5 1844,960.5 1856.1,960.5 1859.85,964.25 1859.85,971.75 1856.1,975.5 1844,975.5 1831.9,975.5 1828.15,979.25 1828.15,986.75 1831.9,990.5 1840.25,990.5 1844,994.25 1844,1005.5 1844,1007 1849.3,1012.3 1857.26,1020.26 1862.56,1020.26 1868.46,1014.36 1873.77,1014.36 1879.07,1019.66 1879.07,1024.96 1870.52,1033.52 1861.96,1042.07 1861.96,1047.37 1867.27,1052.68 1872.57,1052.68 1881.12,1044.12 1889.68,1035.57 1894.98,1035.57 1900.28,1040.87 1900.28,1046.18 1891.73,1054.73 1883.18,1063.28 1883.18,1068.59 1888.48,1073.89 1893.78,1073.89 1902.34,1065.34 1910.89,1056.78 1916.19,1056.78 1921.5,1062.09 1921.5,1067.39 1912.94,1075.94 1904.39,1084.5 1904.39,1089.8 1909.69,1095.1 1915,1095.1 1923.55,1086.55 1932.1,1078 1937.41,1078 1942.71,1083.3 1942.71,1088.6 1934.16,1097.16 1925.6,1105.71 1925.6,1111.01 1930.91,1116.32 1936.21,1116.32 1944.76,1107.76 1953.32,1099.21 1958.62,1099.21 1963.92,1104.51 1963.92,1109.82 1955.37,1118.37 1946.82,1126.92 1946.82,1132.23 1952.12,1137.53 1957.42,1137.53 1965.98,1128.98 1974.53,1120.42 1979.83,1120.42 1985.14,1125.73 1985.14,1131.03 1976.58,1139.58 1968.03,1148.14 1968.03,1153.44 1973.33,1158.74 1978.64,1158.74 1987.19,1150.19 1995.74,1141.64 2001.05,1141.64 2006.35,1146.94 2006.35,1152.24 2000.45,1158.14 2000.45,1163.45 2014,1177 2021.5,1177 2032.75,1177 2036.5,1173.25 2036.5,1164.9 2040.25,1161.15 2047.75,1161.15 2051.5,1164.9 2051.5,1173.25 2055.25,1177 2223,1177 2242,1196 2242,1236.09 J1.59@2242.65,1236.74
/EM_CS2: J1.43@2368.64,1236.74 U1.4 | length 140.5
  Top Layer w15: U1.4@2354.4,1102.13 2354.4,1133.4 v1(2362,1141) v1@2363,1142
  Bottom Layer w6: v1@2363,1142 2368.64,1147.64 J1.43@2368.64,1236.74
/EM_CS2_FLASH: R3.1 U1.1 U4.26 | length 6525
  Top Layer w6: U4.26@793.69,1033.8 793.69,1068.69 797,1072 845,1072 848.75,1072 852.5,1075.75 852.5,1115.57 856.25,1119.32 863.75,1119.32 867.5,1115.57 867.5,1072 867.5,1028.43 871.25,1024.68 878.75,1024.68 882.5,1028.43 882.5,1072 882.5,1115.57 886.25,1119.32 893.75,1119.32 897.5,1115.57 897.5,1072 897.5,1028.43 901.25,1024.68 908.75,1024.68 912.5,1028.43 912.5,1072 912.5,1115.57 916.25,1119.32 923.75,1119.32 927.5,1115.57 927.5,1072 927.5,1028.43 931.25,1024.68 938.75,1024.68 942.5,1028.43 942.5,1072 942.5,1115.57 946.25,1119.32 953.75,1119.32 957.5,1115.57 957.5,1072 957.5,1028.43 961.25,1024.68 968.75,1024.68 972.5,1028.43 972.5,1072 972.5,1115.57 976.25,1119.32 983.75,1119.32 987.5,1115.57 987.5,1072 987.5,1028.43 991.25,1024.68 998.75,1024.68 1002.5,1028.43 1002.5,1072 1002.5,1115.57 1006.25,1119.32 1013.75,1119.32 1017.5,1115.57 1017.5,1072 1017.5,1028.43 1021.25,1024.68 1028.75,1024.68 1032.5,1028.43 1032.5,1072 1032.5,1115.57 1036.25,1119.32 1043.75,1119.32 1047.5,1115.57 1047.5,1072 1047.5,1028.43 1051.25,1024.68 1058.75,1024.68 1062.5,1028.43 1062.5,1068.25 1066.25,1072 1077.5,1072 1080,1072 1085.3,1077.3 1093.26,1085.26 1093.26,1090.56 1065.1,1118.72 1065.1,1124.02 1070.41,1129.32 1075.71,1129.32 1106.52,1098.52 1137.32,1067.71 1142.63,1067.71 1147.93,1073.01 1147.93,1078.32 1117.12,1109.12 1086.32,1139.93 1086.32,1145.23 1091.62,1150.54 1096.92,1150.54 1127.73,1119.73 1158.54,1088.92 1163.84,1088.92 1169.14,1094.23 1169.14,1099.53 1138.34,1130.34 1107.53,1161.14 1107.53,1166.45 1112.83,1171.75 1118.14,1171.75 1148.94,1140.94 1179.75,1110.14 1185.05,1110.14 1190.36,1115.44 1190.36,1120.74 1159.55,1151.55 1128.74,1182.36 1128.74,1187.66 1134.05,1192.96 1139.35,1192.96 1170.16,1162.16 1200.96,1131.35 1206.27,1131.35 1211.57,1136.65 1211.57,1141.96 1180.76,1172.76 1149.96,1203.57 1149.96,1208.87 1155.26,1214.18 1160.56,1214.18 1191.37,1183.37 1222.18,1152.56 1227.48,1152.56 1232.78,1157.87 1232.78,1163.17 1201.98,1193.98 1171.17,1224.78 1171.17,1230.09 1176.47,1235.39 1181.78,1235.39 1212.58,1204.58 1243.39,1173.78 1248.69,1173.78 1254,1179.08 1254,1184.38 1223.19,1215.19 1192.38,1246 1192.38,1251.3 1197.69,1256.6 1202.99,1256.6 1233.8,1225.8 1264.6,1194.99 1269.9,1194.99 1275.21,1200.29 1275.21,1205.6 1244.4,1236.4 1213.6,1267.21 1213.6,1272.51 1218.9,1277.81 1224.2,1277.81 1255.01,1247.01 1285.81,1216.2 1291.12,1216.2 1296.42,1221.51 1296.42,1226.81 1265.62,1257.62 1234.81,1288.42 1234.81,1293.72 1240.11,1299.03 1245.42,1299.03 1276.22,1268.22 1307.03,1237.42 1312.33,1237.42 1317.63,1242.72 1317.63,1248.02 1286.83,1278.83 1256.02,1309.63 1256.02,1314.94 1261.33,1320.24 1266.63,1320.24 1297.44,1289.44 1328.24,1258.63 1333.54,1258.63 1338.85,1263.93 1338.85,1269.24 1308.04,1300.04 1277.24,1330.85 1277.24,1336.15 1282.54,1341.45 1287.84,1341.45 1318.65,1310.65 1349.45,1279.84 1354.76,1279.84 1360.06,1285.15 1360.06,1290.45 1329.26,1321.26 1298.45,1352.06 1298.45,1357.36 1303.75,1362.67 1309.06,1362.67 1339.86,1331.86 1370.67,1301.06 1375.97,1301.06 1381.27,1306.36 1381.27,1311.66 1350.47,1342.47 1319.66,1373.27 1319.66,1378.58 1324.97,1383.88 1330.27,1383.88 1361.07,1353.07 1391.88,1322.27 1397.18,1322.27 1402.49,1327.57 1402.49,1332.88 1371.68,1363.68 1340.88,1394.49 1340.88,1399.79 1346.18,1405.09 1351.48,1405.09 1382.29,1374.29 1413.09,1343.48 1418.4,1343.48 1423.7,1348.79 1423.7,1354.09 1395.55,1382.24 1395.55,1387.55 1403.5,1395.5 1408,1400 1415.5,1400 1426.75,1400 1430.5,1403.75 1430.5,1422.57 1434.25,1426.32 1441.75,1426.32 1445.5,1422.57 1445.5,1400 1445.5,1356.43 1449.25,1352.68 1456.75,1352.68 1460.5,1356.43 1460.5,1400 1460.5,1422.57 1464.25,1426.32 1471.75,1426.32 1475.5,1422.57 1475.5,1400 1475.5,1356.43 1479.25,1352.68 1486.75,1352.68 1490.5,1356.43 1490.5,1400 1490.5,1422.57 1494.25,1426.32 1501.75,1426.32 1505.5,1422.57 1505.5,1400 1505.5,1356.43 1509.25,1352.68 1516.75,1352.68 1520.5,1356.43 1520.5,1396.25 1524.25,1400 1552,1400 2198,1400 2234,1364 2234,1275 2253,1256 2253,1076 2292,1037 2357,1037 2380,1014 2380,946 2369,935 2294,935 2280,949 v1(2280,960)
  Top Layer w15: U1.1@2279.6,993.87 2279.6,960.4 v1(2280,960)
  Bottom Layer w8: R3.1@2280,926.56 v1(2280,960)
/EM_CS2_SRAM: R2.1 U1.3 U3.6 | length 6299.7
  Top Layer w6: v1@1547,750 1547,1026 1547,1079.75 1543.25,1083.5 1500.75,1083.5 1497,1087.25 1497,1094.75 1500.75,1098.5 1547,1098.5 1593.25,1098.5 1597,1102.25 1597,1109.75 1593.25,1113.5 1547,1113.5 1500.75,1113.5 1497,1117.25 1497,1124.75 1500.75,1128.5 1547,1128.5 1593.25,1128.5 1597,1132.25 1597,1139.75 1593.25,1143.5 1547,1143.5 1500.75,1143.5 1497,1147.25 1497,1154.75 1500.75,1158.5 1547,1158.5 1593.25,1158.5 1597,1162.25 1597,1169.75 1593.25,1173.5 1547,1173.5 1500.75,1173.5 1497,1177.25 1497,1184.75 1500.75,1188.5 1547,1188.5 1593.25,1188.5 1597,1192.25 1597,1199.75 1593.25,1203.5 1547,1203.5 1500.75,1203.5 1497,1207.25 1497,1214.75 1500.75,1218.5 1547,1218.5 1593.25,1218.5 1597,1222.25 1597,1229.75 1593.25,1233.5 1547,1233.5 1500.75,1233.5 1497,1237.25 1497,1244.75 1500.75,1248.5 1547,1248.5 1593.25,1248.5 1597,1252.25 1597,1259.75 1593.25,1263.5 1547,1263.5 1500.75,1263.5 1497,1267.25 1497,1274.75 1500.75,1278.5 1547,1278.5 1593.25,1278.5 1597,1282.25 1597,1289.75 1593.25,1293.5 1547,1293.5 1500.75,1293.5 1497,1297.25 1497,1304.75 1500.75,1308.5 1547,1308.5 1593.25,1308.5 1597,1312.25 1597,1319.75 1593.25,1323.5 1547,1323.5 1500.75,1323.5 1497,1327.25 1497,1334.75 1500.75,1338.5 1543.25,1338.5 1547,1342.25 1547,1353.5 1547,1361 1572,1386 2191,1386 2219,1358 2219,1270 2240,1249 2240,1069 2285,1024 2341.4,1024 2354.4,1011 U1.3@2354.4,993.87
  Top Layer w15: U3.6@1202.77,256.62 1202.77,222.23 v1@1203,222 ; v1(2354.4,960.4) U1.3@2354.4,993.87
  Signal Layer 3 w6: v1@1203,217 1203,307 1218,322 1532,322 1547,337 1547,352 1547,359.5 1547,370.75 1550.75,374.5 1603.25,374.5 1607,378.25 1607,385.75 1603.25,389.5 1547,389.5 1490.75,389.5 1487,393.25 1487,400.75 1490.75,404.5 1547,404.5 1603.25,404.5 1607,408.25 1607,415.75 1603.25,419.5 1547,419.5 1490.75,419.5 1487,423.25 1487,430.75 1490.75,434.5 1547,434.5 1603.25,434.5 1607,438.25 1607,445.75 1603.25,449.5 1547,449.5 1490.75,449.5 1487,453.25 1487,460.75 1490.75,464.5 1547,464.5 1603.25,464.5 1607,468.25 1607,475.75 1603.25,479.5 1547,479.5 1490.75,479.5 1487,483.25 1487,490.75 1490.75,494.5 1547,494.5 1603.25,494.5 1607,498.25 1607,505.75 1603.25,509.5 1547,509.5 1490.75,509.5 1487,513.25 1487,520.75 1490.75,524.5 1547,524.5 1603.25,524.5 1607,528.25 1607,535.75 1603.25,539.5 1547,539.5 1490.75,539.5 1487,543.25 1487,550.75 1490.75,554.5 1547,554.5 1603.25,554.5 1607,558.25 1607,565.75 1603.25,569.5 1547,569.5 1490.75,569.5 1487,573.25 1487,580.75 1490.75,584.5 1547,584.5 1603.25,584.5 1607,588.25 1607,595.75 1603.25,599.5 1547,599.5 1490.75,599.5 1487,603.25 1487,610.75 1490.75,614.5 1547,614.5 1603.25,614.5 1607,618.25 1607,625.75 1603.25,629.5 1550.75,629.5 1547,633.25 1547,654 1547,658 v1@1547,750
  Bottom Layer w8: v1@2354.4,958.4 2354.4,927.16 R2.1@2355,926.56
  other v1: 1203,213 1547,752
/EM_OE: J1.44@2368.64,1329.26 U3.41 U4.28 | length 6476.4
  Top Layer w8: v1@754,1076 754.32,1075.68 U4.28@754.32,1033.8
  Top Layer w15: v1(1139.78,666.22) U3.41@1139.78,709.38
  Signal Layer 3 w6: v1@754,1073 927,1073 939,1061 939,1048 939,1042.9 942.4,1039.5 968.74,1039.5 972.14,1036.1 972.14,1025.9 968.74,1022.5 939,1022.5 909.26,1022.5 905.86,1019.1 905.86,1008.9 909.26,1005.5 939,1005.5 968.74,1005.5 972.14,1002.1 972.14,991.9 968.74,988.5 939,988.5 909.26,988.5 905.86,985.1 905.86,974.9 909.26,971.5 939,971.5 968.74,971.5 972.14,968.1 972.14,957.9 968.74,954.5 939,954.5 909.26,954.5 905.86,951.1 905.86,940.9 909.26,937.5 939,937.5 968.74,937.5 972.14,934.1 972.14,923.9 968.74,920.5 939,920.5 909.26,920.5 905.86,917.1 905.86,906.9 909.26,903.5 939,903.5 968.74,903.5 972.14,900.1 972.14,889.9 968.74,886.5 939,886.5 909.26,886.5 905.86,883.1 905.86,872.9 909.26,869.5 939,869.5 968.74,869.5 972.14,866.1 972.14,855.9 968.74,852.5 939,852.5 909.26,852.5 905.86,849.1 905.86,838.9 909.26,835.5 939,835.5 968.74,835.5 972.14,832.1 972.14,821.9 968.74,818.5 939,818.5 909.26,818.5 905.86,815.1 905.86,804.9 909.26,801.5 939,801.5 968.74,801.5 972.14,798.1 972.14,787.9 968.74,784.5 939,784.5 909.26,784.5 905.86,781.1 905.86,770.9 909.26,767.5 939,767.5 968.74,767.5 972.14,764.1 972.14,753.9 968.74,750.5 942.4,750.5 939,747.1 939,729 939,724 951,712 1098,712 v1@1139.78,670.22
  Bottom Layer w6: v1@1139.78,670.22 v1(1139.78,666.22) 1139.78,610.22 1148,602 1255,602 1292,639 1532,639 1612,719 1612,771 1612,783.1 1608.6,786.5 1561.4,786.5 1558,789.9 1558,800.1 1561.4,803.5 1612,803.5 1658.1,803.5 1661.5,806.9 1661.5,817.1 1658.1,820.5 1612,820.5 1561.4,820.5 1558,823.9 1558,834.1 1561.4,837.5 1612,837.5 1658.1,837.5 1661.5,840.9 1661.5,851.1 1658.1,854.5 1612,854.5 1561.4,854.5 1558,857.9 1558,868.1 1561.4,871.5 1612,871.5 1658.1,871.5 1661.5,874.9 1661.5,885.1 1658.1,888.5 1612,888.5 1561.4,888.5 1558,891.9 1558,902.1 1561.4,905.5 1608.6,905.5 1612,908.9 1612,922.5 1612,931 1619.84,938.84 1619.84,943.64 1586.46,977.02 1586.46,981.83 1593.67,989.04 1598.48,989.04 1634.26,953.26 1667.81,919.71 1672.62,919.71 1679.83,926.92 1679.83,931.73 1646.28,965.28 1610.5,1001.06 1610.5,1005.87 1617.71,1013.08 1622.52,1013.08 1658.3,977.3 1691.85,943.75 1696.66,943.75 1703.87,950.96 1703.87,955.77 1670.32,989.32 1634.54,1025.1 1634.54,1029.91 1641.76,1037.12 1646.56,1037.12 1682.34,1001.34 1718.12,965.56 1722.93,965.56 1730.14,972.78 1730.14,977.59 1694.36,1013.36 1658.59,1049.14 1658.59,1053.95 1665.8,1061.17 1670.61,1061.17 1706.39,1025.39 1742.17,989.61 1746.97,989.61 1754.19,996.82 1754.19,1001.63 1718.41,1037.41 1682.63,1073.19 1682.63,1077.99 1689.84,1085.21 1694.65,1085.21 1730.43,1049.43 1763.83,1016.03 1768.64,1016.03 1775.85,1023.24 1775.85,1028.05 1742.45,1061.45 1706.67,1097.23 1706.67,1102.04 1713.88,1109.25 1718.69,1109.25 1754.47,1073.47 1779.05,1048.89 1783.86,1048.89 1791.07,1056.1 1791.07,1060.91 1768.89,1083.09 1768.89,1087.89 1772.5,1091.5 1787,1106 1789.65,1108.65 1789.65,1113.95 1778.81,1124.8 1778.81,1130.1 1784.11,1135.4 1789.42,1135.4 1802.91,1121.91 1816.4,1108.42 1821.71,1108.42 1827.01,1113.72 1827.01,1119.02 1813.52,1132.52 1800.02,1146.01 1800.02,1151.31 1805.33,1156.62 1810.63,1156.62 1824.12,1143.12 1837.62,1129.63 1842.92,1129.63 1848.22,1134.93 1848.22,1140.24 1834.73,1153.73 1821.24,1167.22 1821.24,1172.53 1826.54,1177.83 1831.84,1177.83 1845.34,1164.34 1858.83,1150.84 1864.13,1150.84 1869.44,1156.15 1869.44,1161.45 1855.94,1174.94 1842.45,1188.44 1842.45,1193.74 1847.75,1199.04 1853.06,1199.04 1866.55,1185.55 1880.04,1172.06 1885.35,1172.06 1890.65,1177.36 1890.65,1182.66 1877.16,1196.16 1863.66,1209.65 1863.66,1214.95 1868.97,1220.26 1874.27,1220.26 1887.76,1206.76 1901.26,1193.27 1906.56,1193.27 1911.86,1198.57 1911.86,1203.88 1898.37,1217.37 1884.88,1230.86 1884.88,1236.17 1890.18,1241.47 1895.48,1241.47 1908.98,1227.98 1922.47,1214.48 1927.77,1214.48 1933.08,1219.79 1933.08,1225.09 1919.58,1238.58 1906.09,1252.08 1906.09,1257.38 1911.39,1262.68 1916.7,1262.68 1930.19,1249.19 1943.68,1235.7 1948.99,1235.7 1954.29,1241 1954.29,1246.3 1940.8,1259.8 1927.3,1273.29 1927.3,1278.59 1932.61,1283.9 1937.91,1283.9 1951.4,1270.4 1964.9,1256.91 1970.2,1256.91 1975.5,1262.21 1975.5,1267.52 1962.01,1281.01 1948.52,1294.5 1948.52,1299.81 1953.82,1305.11 1959.12,1305.11 1972.62,1291.62 1986.11,1278.12 1991.41,1278.12 1996.72,1283.43 1996.72,1288.73 1983.22,1302.22 1969.73,1315.72 1969.73,1321.02 1975.03,1326.32 1980.34,1326.32 1993.83,1312.83 2007.32,1299.34 2012.63,1299.34 2017.93,1304.64 2017.93,1309.94 2004.44,1323.44 1990.94,1336.93 1990.94,1342.23 1996.25,1347.54 2001.55,1347.54 2012.39,1336.69 2017.69,1336.69 2022.69,1336.69 2047,1361 2047,1366 2117,1436 2303,1436 2368.64,1370.36 J1.44@2368.64,1329.26
  other v1: 754,1077
/EM_WE: J1.45@2352.89,1236.74 U2.16 U3.17 U4.11 | length 6536.4
  Top Layer w6: U4.11@557.47,258.2 557,257.73 557,44 569,32 592,32 595.75,32 599.5,35.75 599.5,36.25 603.25,40 610.75,40 614.5,36.25 614.5,32 614.5,27.75 618.25,24 625.75,24 629.5,27.75 629.5,32 629.5,36.25 633.25,40 640.75,40 644.5,36.25 644.5,32 644.5,27.75 648.25,24 655.75,24 659.5,27.75 659.5,32 659.5,36.25 663.25,40 670.75,40 674.5,36.25 674.5,32 674.5,27.75 678.25,24 685.75,24 689.5,27.75 689.5,32 689.5,36.25 693.25,40 700.75,40 704.5,36.25 704.5,32 704.5,27.75 708.25,24 715.75,24 719.5,27.75 719.5,32 719.5,36.25 723.25,40 730.75,40 734.5,36.25 734.5,32 734.5,27.75 738.25,24 745.75,24 749.5,27.75 749.5,32 749.5,36.25 753.25,40 760.75,40 764.5,36.25 764.5,32 764.5,27.75 768.25,24 775.75,24 779.5,27.75 779.5,32 779.5,36.25 783.25,40 790.75,40 794.5,36.25 794.5,32 794.5,27.75 798.25,24 805.75,24 809.5,27.75 809.5,32 809.5,36.25 813.25,40 820.75,40 824.5,36.25 824.5,32 824.5,27.75 828.25,24 835.75,24 839.5,27.75 839.5,32 839.5,36.25 843.25,40 850.75,40 854.5,36.25 854.5,32 854.5,27.75 858.25,24 865.75,24 869.5,27.75 869.5,32 869.5,36.25 873.25,40 880.75,40 884.5,36.25 884.5,32 884.5,27.75 888.25,24 895.75,24 899.5,27.75 899.5,32 899.5,36.25 903.25,40 910.75,40 914.5,36.25 914.5,32 914.5,27.75 918.25,24 925.75,24 929.5,27.75 929.5,32 929.5,36.25 933.25,40 940.75,40 944.5,36.25 944.5,32 944.5,27.75 948.25,24 955.75,24 959.5,27.75 959.5,32 959.5,36.25 963.25,40 970.75,40 974.5,36.25 974.5,32 974.5,27.75 978.25,24 985.75,24 989.5,27.75 989.5,32 989.5,36.25 993.25,40 1000.75,40 1004.5,36.25 1004.5,32 1004.5,27.75 1008.25,24 1015.75,24 1019.5,27.75 1019.5,32 1019.5,36.25 1023.25,40 1030.75,40 1034.5,36.25 1034.5,32 1034.5,27.75 1038.25,24 1045.75,24 1049.5,27.75 1049.5,32 1049.5,36.25 1053.25,40 1060.75,40 1064.5,36.25 1064.5,32 1064.5,27.75 1068.25,24 1075.75,24 1079.5,27.75 1079.5,32 1079.5,36.25 1083.25,40 1090.75,40 1094.5,36.25 1094.5,32 1094.5,27.75 1098.25,24 1105.75,24 1109.5,27.75 1109.5,32 1109.5,36.25 1113.25,40 1120.75,40 1124.5,36.25 1124.5,32 1124.5,27.75 1128.25,24 1135.75,24 1139.5,27.75 1139.5,32 1139.5,36.25 1143.25,40 1150.75,40 1154.5,36.25 1154.5,32 1154.5,27.75 1158.25,24 1165.75,24 1169.5,27.75 1169.5,32 1169.5,36.25 1173.25,40 1180.75,40 1184.5,36.25 1184.5,32 1184.5,27.75 1188.25,24 1195.75,24 1199.5,27.75 1199.5,32 1199.5,36.25 1203.25,40 1210.75,40 1214.5,36.25 1214.5,32 1214.5,27.75 1218.25,24 1225.75,24 1229.5,27.75 1229.5,32 1229.5,36.25 1233.25,40 1240.75,40 1244.5,36.25 1244.5,32 1244.5,27.75 1248.25,24 1255.75,24 1259.5,27.75 1259.5,28.25 1263.25,32 1381,32 1389,32 1398,41 1398,142 1423,167 1538,167 1549.23,178.23 U3.17@1549.23,256.62 1549.23,293.23 1587,331 1713,331 1734,310 1734,203 1665,134 1467,134 1455,122 1455,53 1463,45 1920,45 1932,57 1932,70 1932,100.12 1928.6,103.52 1910.02,103.52 1906.62,106.92 1906.62,117.12 1910.02,120.52 1932,120.52 1949.45,120.52 1952.85,123.92 1952.85,134.12 1949.45,137.52 1932,137.52 1910.02,137.52 1906.62,140.92 1906.62,151.12 1910.02,154.52 1932,154.52 1935.03,154.52 1938.43,157.92 1938.43,168.12 1935.03,171.52 1932,171.52 1910.02,171.52 1906.62,174.92 1906.62,185.12 1910.02,188.52 1932,188.52 1950.6,188.52 1954,191.92 1954,202.12 1950.6,205.52 1932,205.52 1909.84,205.52 1906.43,208.92 1906.43,219.12 1909.84,222.52 1932,222.52 1933.97,222.52 1937.37,225.92 1937.37,236.12 1933.97,239.52 1932,239.52 1908.48,239.52 1905.08,242.92 1905.08,253.12 1908.48,256.52 1932,256.52 1937.71,256.52 1941.11,259.92 1941.11,270.12 1937.71,273.52 1932,273.52 1909.84,273.52 1906.44,276.92 1906.44,287.12 1909.84,290.52 1932,290.52 1937.7,290.52 1941.1,293.92 1941.1,304.12 1937.7,307.52 1932,307.52 1908.02,307.52 1904.62,310.92 1904.62,321.12 1908.02,324.52 1932,324.52 1932.97,324.52 1936.37,327.92 1936.37,338.12 1932.97,341.52 1932,341.52 1908.02,341.52 1904.62,344.92 1904.62,355.12 1908.02,358.52 1928.6,358.52 1932,361.92 1932,375.52 1932,384.02 v1(1959.99,412.01)
  Top Layer w15: v1@1963.99,408.01 U2.16@2003.64,408.01 ; v1@1963.99,409.01 U2.16@2003.64,409.01
  Bottom Layer w6: v1@1963.99,408.01 1988.01,408.01 2004,424 2004,428.5 2004,439.75 2007.75,443.5 2016.25,443.5 2020,447.25 2020,454.75 2016.25,458.5 2004,458.5 1991.75,458.5 1988,462.25 1988,469.75 1991.75,473.5 2004,473.5 2016.25,473.5 2020,477.25 2020,484.75 2016.25,488.5 2004,488.5 1991.75,488.5 1988,492.25 1988,499.75 1991.75,503.5 2004,503.5 2016.25,503.5 2020,507.25 2020,514.75 2016.25,518.5 2004,518.5 1991.75,518.5 1988,522.25 1988,529.75 1991.75,533.5 2004,533.5 2016.25,533.5 2020,537.25 2020,544.75 2016.25,548.5 2004,548.5 1991.75,548.5 1988,552.25 1988,559.75 1991.75,563.5 2004,563.5 2016.25,563.5 2020,567.25 2020,574.75 2016.25,578.5 2004,578.5 1991.75,578.5 1988,582.25 1988,589.75 1991.75,593.5 2004,593.5 2016.25,593.5 2020,597.25 2020,604.75 2016.25,608.5 2004,608.5 1991.75,608.5 1988,612.25 1988,619.75 1991.75,623.5 2004,623.5 2016.25,623.5 2020,627.25 2020,634.75 2016.25,638.5 2004,638.5 1991.75,638.5 1988,642.25 1988,649.75 1991.75,653.5 2004,653.5 2016.25,653.5 2020,657.25 2020,664.75 2016.25,668.5 2004,668.5 1991.75,668.5 1988,672.25 1988,679.75 1991.75,683.5 2004,683.5 2016.25,683.5 2020,687.25 2020,694.75 2016.25,698.5 2004,698.5 1991.75,698.5 1988,702.25 1988,709.75 1991.75,713.5 2004,713.5 2016.25,713.5 2020,717.25 2020,724.75 2016.25,728.5 2004,728.5 1991.75,728.5 1988,732.25 1988,739.75 1991.75,743.5 2004,743.5 2016.25,743.5 2020,747.25 2020,754.75 2016.25,758.5 2004,758.5 1991.75,758.5 1988,762.25 1988,769.75 1991.75,773.5 2004,773.5 2016.25,773.5 2020,777.25 2020,784.75 2016.25,788.5 2004,788.5 1991.75,788.5 1988,792.25 1988,799.75 1991.75,803.5 2004,803.5 2016.25,803.5 2020,807.25 2020,814.75 2016.25,818.5 2004,818.5 1991.75,818.5 1988,822.25 1988,829.75 1991.75,833.5 2000.25,833.5 2004,837.25 2004,848.5 2004,856 2037,889 2052.34,904.34 2052.34,909.64 2040.41,921.57 2040.41,926.87 2045.72,932.17 2051.02,932.17 2065.6,917.6 2080.17,903.02 2085.48,903.02 2090.78,908.32 2090.78,913.63 2076.2,928.2 2061.63,942.78 2061.63,948.08 2066.93,953.39 2072.23,953.39 2086.81,938.81 2101.39,924.23 2106.69,924.23 2111.99,929.54 2111.99,934.84 2097.42,949.42 2082.84,963.99 2082.84,969.3 2088.14,974.6 2093.45,974.6 2108.02,960.02 2122.6,945.45 2127.9,945.45 2133.21,950.75 2133.21,956.05 2118.63,970.63 2104.05,985.21 2104.05,990.51 2109.36,995.81 2114.66,995.81 2129.24,981.24 2143.81,966.66 2149.12,966.66 2154.42,971.96 2154.42,977.27 2139.84,991.84 2125.27,1006.42 2125.27,1011.72 2130.57,1017.03 2135.87,1017.03 2150.45,1002.45 2165.03,987.87 2170.33,987.87 2175.63,993.18 2175.63,998.48 2161.06,1013.06 2146.48,1027.63 2146.48,1032.94 2151.78,1038.24 2157.09,1038.24 2171.66,1023.66 2186.24,1009.09 2191.54,1009.09 2196.85,1014.39 2196.85,1019.69 2182.27,1034.27 2167.69,1048.85 2167.69,1054.15 2173,1059.45 2178.3,1059.45 2192.88,1044.88 2207.45,1030.3 2212.76,1030.3 2218.06,1035.6 2218.06,1040.91 2203.48,1055.48 2188.91,1070.06 2188.91,1075.36 2194.21,1080.67 2199.51,1080.67 2214.09,1066.09 2228.67,1051.51 2233.97,1051.51 2239.27,1056.82 2239.27,1062.12 2227.35,1074.05 2227.35,1079.35 2230,1082 2240,1092 2281,1092 2352.89,1163.89 J1.45@2352.89,1236.74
